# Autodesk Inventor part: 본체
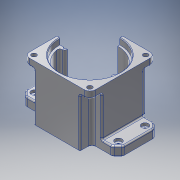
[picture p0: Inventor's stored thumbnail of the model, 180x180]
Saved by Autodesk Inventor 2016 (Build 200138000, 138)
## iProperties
Created: 2017-01
Part Number: 본체
Material: 알루미늄 6061
Document SubType Name: Modeling
Designer: Owner
Density: 2.7 g/cm^3
Appearance: 알루미늄 - 평지
Mass: 877.431 g
Surface Area: 768.445 cm^2
Volume: 324.975 cm^3
Author: Owner
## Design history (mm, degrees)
sketch "스케치1"
  geometry: L1 (-33, 47)-(33, 47); L2 (33, 47)-(33, -47); L3 (33, -47)-(-33, -47); L4 (-33, -47)-(-33, 47); L5 (-33, 47)-(33, -47); L6 (33, 47)-(-33, -47); 1 further point
  constraints: 12 end point, 2 midpoint, 2 parallel, 1 horizontal, 1 perpendicular
  dimensions: "d0" = 66 distance of L2.end L3.end; "d1" = 94 distance of L1.end L2.end
extrude "돌출1" new body sketch "스케치1" distance "d2" = 80; taper "d3" = 0 deg
sketch "스케치2"
  geometry: L1 (-33, 0)-(-33, 80) reference; L2 (-33, 0)-(-70, 0); L3 (-70, 0)-(-70, 13); L4 (-70, 13)-(-47, 13); L5 (-47, 13)-(-47, 70); L6 (-47, 70)-(-33, 70); 1 further point
  constraints: 10 end point, 4 perpendicular, 1 horizontal, 1 point on line
  dimensions: "d4" = 70 distance between parallel lines of L6 L2; "d5" = 13 distance between parallel lines of L2 L4; "d6" = 70 distance from line of L3 point (0, 0); "d7" = 47 distance from line of point (0, 0) L5
extrude "돌출2" join sketch "스케치2" stored distance "d8" = 60; taper "d9" = 0 deg
sketch "스케치3"
  geometry: L1 (-47, 47)-(47, 47); L2 (47, 47)-(47, -47); L3 (47, -47)-(-47, -47); L4 (-47, -47)-(-47, 47); L5 (-47, 47)-(47, -47); L6 (47, 47)-(-47, -47); 1 further point
  constraints: 12 end point, 2 midpoint, 2 parallel, 1 horizontal, 1 perpendicular
  dimensions: "d10" = 94 distance of L2.end L3.end; "d11" = 94 distance of L1.end L2.end
extrude "돌출3" join sketch "스케치3" distance "d12" = 10; taper "d13" = 0 deg
fillet "모깎기1" dims "d14" = 8
chamfer "모따기1" distance "d15" = 8; stored, may be unused: second distance "d16" = 2, angle "d17" = 45 deg
fillet "모깎기2" dims "d32" = 5
fillet "모깎기3" dims "d33" = 5
node "작업 평면1"
sketch "스케치5"
  geometry: L1 (-60, 19)-(60, 19); L2 (60, 19)-(60, -19); L3 (60, -19)-(-60, -19); L4 (-60, -19)-(-60, 19); L5 (-60, 19)-(60, -19); L6 (60, 19)-(-60, -19); 5 further points
  constraints: 12 end point, 4 coincident, 2 midpoint, 2 parallel, 1 horizontal, 1 perpendicular
  dimensions: "d35" = 120 distance of L2.end L3.end; "d36" = 38 distance of L1.end L2.end
hole "구멍1" sketch "스케치5" at (-60, 19), (60, -19), (60, 19), (-60, -19) diameter "d37" = 4; stored, may be unused: countersink angle "d41" = 90 deg, drill point angle "d43" = 118 deg; dims "d38" = 6, "d39" = 10, "d40" = 4, "d42" = 8
sketch "스케치6"
  geometry: C1 r 43 at (0, 0); 1 further point
  constraints: 1 centre point, 1 coincident
  dimensions: "d53" = 86 diameter of C1
extrude "돌출5" cut sketch "스케치6" distance "d54" = 9; taper "d55" = 0 deg
sketch "스케치7"
  geometry: C1 r 40 at (0, 0); 1 further point
  constraints: 1 centre point, 1 coincident
  dimensions: "d56" = 80 diameter of C1
extrude "돌출6" cut sketch "스케치7" distance "d57" = 62; taper "d58" = 0 deg
sketch "스케치9"
  geometry: L1 (-38, -30)-(-59.929, -30) reference; L2 (-33, -35)-(-33, -47) reference; L3 (-33, -47)-(33, -47) reference; L4 (33, -47)-(33, -35) reference; L5 (38, -30)-(59.929, -30) reference; L6 (68.536, -23.464)-(63.464, -28.536) reference; L7 (70, -19.929)-(70, 19.929) reference; L8 (63.464, 28.536)-(68.536, 23.464) reference; L9 (59.929, 30)-(38, 30) reference; L10 (33, 35)-(33, 47) reference; L11 (33, 47)-(-33, 47) reference; L12 (-33, 47)-(-33, 35) reference; L13 (-59.929, 30)-(-38, 30) reference; L14 (-68.536, 23.464)-(-63.464, 28.536) reference; L15 (-70, -19.929)-(-70, 19.929) reference; L16 (-63.464, -28.536)-(-68.536, -23.464) reference; L17 (-32, 46)-(32, 46); L18 (32, 46)-(32, 35); L19 (38, 29)-(59.929, 29); L20 (62.757, 27.828)-(67.828, 22.757); L21 (69, 19.929)-(69, -19.929); L22 (67.828, -22.757)-(62.757, -27.828); L23 (59.929, -29)-(38, -29); L24 (32, -35)-(32, -46); L25 (32, -46)-(-32, -46); L26 (-32, -46)-(-32, -35); L27 (-38, -29)-(-59.929, -29); L28 (-62.757, -27.828)-(-67.828, -22.757); L29 (-69, -19.929)-(-69, 19.929); L30 (-67.828, 22.757)-(-62.757, 27.828); L31 (-59.929, 29)-(-38, 29); L32 (-32, 35)-(-32, 46); C1 r 2 at (-60, 19) reference; C2 r 2 at (60, 19) reference; C3 r 2 at (-60, -19) reference; C4 r 2 at (60, -19) reference; A1 r 5 centre (-59.929, -25) between (-63.464, -28.536) and (-59.929, -30) reference; A2 r 5 centre (-38, -35) between (-33, -35) and (-38, -30) reference; A3 r 5 centre (38, -35) between (38, -30) and (33, -35) reference; A4 r 5 centre (59.929, -25) between (59.929, -30) and (63.464, -28.536) reference; A5 r 5 centre (65, -19.929) between (68.536, -23.464) and (70, -19.929) reference; A6 r 5 centre (65, 19.929) between (70, 19.929) and (68.536, 23.464) reference; A7 r 5 centre (59.929, 25) between (63.464, 28.536) and (59.929, 30) reference; A8 r 5 centre (38, 35) between (33, 35) and (38, 30) reference; A9 r 5 centre (-38, 35) between (-38, 30) and (-33, 35) reference; A10 r 5 centre (-59.929, 25) between (-59.929, 30) and (-63.464, 28.536) reference; A11 r 5 centre (-65, 19.929) between (-68.536, 23.464) and (-70, 19.929) reference; A12 r 5 centre (-65, -19.929) between (-70, -19.929) and (-68.536, -23.464) reference; A13 r 6 centre (38, 35) between (32, 35) and (38, 29); A14 r 4 centre (59.929, 25) between (62.757, 27.828) and (59.929, 29); A15 r 4 centre (65, 19.929) between (69, 19.929) and (67.828, 22.757); A16 r 4 centre (65, -19.929) between (67.828, -22.757) and (69, -19.929); A17 r 4 centre (59.929, -25) between (59.929, -29) and (62.757, -27.828); A18 r 6 centre (38, -35) between (38, -29) and (32, -35); A19 r 6 centre (-38, -35) between (-32, -35) and (-38, -29); A20 r 4 centre (-59.929, -25) between (-62.757, -27.828) and (-59.929, -29); A21 r 4 centre (-65, -19.929) between (-69, -19.929) and (-67.828, -22.757); A22 r 4 centre (-65, 19.929) between (-67.828, 22.757) and (-69, 19.929); A23 r 4 centre (-59.929, 25) between (-59.929, 29) and (-62.757, 27.828); A24 r 6 centre (-38, 35) between (-38, 29) and (-32, 35); 1 further point
  constraints: 32 end point, 24 point on circle, 12 centre point, 27 other
  dimensions: "d66" = 1 distance between parallel lines of L11 L17
extrude "돌출7" cut sketch "스케치9" distance "d67" = 1; taper "d68" = 0 deg
sketch "스케치10"
  geometry: C1 r 21 at (0, 11); C2 r 15 at (0, -22); 1 further point
  constraints: 2 centre point, 2 vertical alignment
  dimensions: "d69" = 42 diameter of C1; "d70" = 30 diameter of C2; "d71" = 11 distance of point (0, 0) C1.centre; "d72" = 22 distance of point (0, 0) C2.centre
extrude "돌출8" join sketch "스케치10" distance "d73" = 7; taper "d74" = 0 deg
sketch "스케치11"
  geometry: C1 r 27.5 at (0, 11); 1 further point
  constraints: 1 centre point, 1 vertical alignment
  dimensions: "d75" = 55 diameter of C1; "d76" = 11 distance of point (0, 0) C1.centre
extrude "돌출9" join sketch "스케치11" distance "d77" = 7; taper "d78" = 0 deg
sketch "스케치12"
  geometry: L1 (11, -7)-(11, 16); L2 (23.5, 1)-(27, 1); L3 (28.5, 16)-(28.5, 6); L4 (28.5, 6)-(23.5, 6); L5 (23.5, 6)-(23.5, 1); L6 (27, 1)-(27, -7); L7 (-16.5, -7)-(38.5, -7) reference; L8 (27, -7)-(11, -7); L9 (28.5, 16)-(11, 16); L10 (32, 16)-(-8.773, 16) reference; 1 further point
  constraints: 16 end point, 3 vertical, 2 midpoint, 2 perpendicular, 1 collinear, 1 horizontal, 1 point on line
  dimensions: "d79" = 11 distance from line of point (0, 0) L1; "d80" = 23 distance of L1.start L1.end; "d81" = 8 distance of L2.end L6.end; "d82" = 5 distance of L4.end L2.start; "d83" = 25 diameter of L5 L1; "d85" = 35 diameter of L3 L1; "d86" = 32 diameter of L6 L1
revolve "회전1" sketch "스케치12" stored, may be unused: angle "d87" = 90 deg
sketch "스케치13"
  geometry: L1 (-20, 16)-(-20, 8); L2 (-8.773, 16)-(-37, 16) reference; L3 (-20, 16)-(-31, 16); L4 (-31, 16)-(-31, 9); L5 (-31, 9)-(-29.5, 9); L6 (-29.5, 8)-(-20, 8); L7 (-29.5, 8)-(-29.5, 9); 1 further point
  constraints: 12 end point, 3 vertical, 2 point on line, 1 parallel
  dimensions: "d88" = 8 distance of L1.start L1.end; "d89" = 20 distance from line of point (0, 0) L1; "d90" = 22 diameter of L4 L1; "d91" = 19 diameter of L7 L1; "d92" = 1 distance of L6.start L5.end; "d93" = 7 distance of L3.end L4.end
revolve "회전2" sketch "스케치13" stored, may be unused: angle "d94" = 90 deg
sketch "스케치14"
  geometry: A1 r 40 centre (0, 0) between (39.148, 8.214) and (39.148, -8.214) reference; A2 r 4 centre (36, 0) between (35.852, 3.997) and (35.852, -3.997); A3 r 3.5 centre (35.722, 7.495) between (35.852, 3.997) and (39.148, 8.214); A4 r 3.5 centre (35.722, -7.495) between (39.148, -8.214) and (35.852, -3.997); 1 further point
  constraints: 8 point on circle, 5 tangent, 3 centre point, 1 horizontal alignment
  dimensions: "d95" = 8 diameter of A2; "d96" = 7 diameter of A3; "d97" = 7 diameter of A4
extrude "돌출10" join sketch "스케치14" stored distance "d98" = 7; taper "d99" = 0 deg
hole "구멍3" diameter "d102" = 3.242; stored, may be unused: countersink angle "d106" = 90 deg, drill point angle "d108" = 118 deg; dims "d100" = 10, "d101" = 10, "d103" = 7, "d104" = 4, "d105" = 2, "d107" = 9
chamfer "모따기2" distance "d111" = 1; stored, may be unused: second distance "d112" = 2, angle "d113" = 45 deg
fillet "모깎기4" dims "d114" = 0.3
fillet "모깎기5" dims "d115" = 3
sketch "스케치15"
  geometry: L1 (-40, 40)-(40, 40); L2 (40, 40)-(40, -40); L3 (40, -40)-(-40, -40); L4 (-40, -40)-(-40, 40); L5 (-40, 40)-(40, -40); L6 (40, 40)-(-40, -40); 5 further points
  constraints: 12 end point, 4 coincident, 2 midpoint, 2 parallel, 1 horizontal, 1 perpendicular
  dimensions: "d116" = 80 distance of L2.end L3.end; "d117" = 80 distance of L1.end L2.end
hole "구멍4" sketch "스케치15" at (-40, 40), (-40, -40), (40, -40), (40, 40) diameter "d118" = 7; stored, may be unused: countersink angle "d122" = 90 deg, drill point angle "d124" = 118 deg; dims "d119" = 7, "d120" = 4, "d121" = 2, "d123" = 9
fillet "모깎기6" dims "d125" = 2
fillet "모깎기7" dims "d126" = 2
fillet "모깎기8" dims "d127" = 2
fillet "모깎기9" dims "d128" = 2
fillet "모깎기10" dims "d129" = 1
sketch "스케치16"
  geometry: L1 (0, 0)-(78, 0) reference; 2 further points
  constraints: 1 vertical alignment, 1 other
  dimensions: "d130" = 40 distance from line of L1 point (39, 40)
feature "엠보싱1" sketch "스케치16" dims "d131" = 0.5, "d132" = 0
fillet "모깎기11" dims "d133" = 2
fillet "모깎기12" dims "d134" = 2
fillet "모깎기13" dims "d135" = 2
sketch "스케치17"
  geometry: L1 (0, 68.961)-(-81.954, 68.961); L2 (-81.954, 68.961)-(-81.954, 0); L3 (-81.954, 0)-(0, 0); L4 (0, 0)-(0, 68.961); 1 further point
  constraints: 8 end point, 2 parallel, 1 horizontal, 1 perpendicular
extrude "돌출11" cut sketch "스케치17" stored distance "d136" = 10; taper "d137" = 0 deg
node "솔리드1"
mirror "대칭1"
mirror "대칭4"
node "투영된 루프1"
other parameters: "d34" = 13
